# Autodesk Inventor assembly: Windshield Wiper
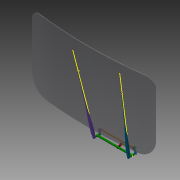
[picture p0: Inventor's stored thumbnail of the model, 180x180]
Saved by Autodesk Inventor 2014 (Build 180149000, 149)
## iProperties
Created: 2006-03
Part Number: Windshield Wiper
Document SubType Name: Assembly
Designer: debonom
Mass: 23655.8 g
Surface Area: 27679.2 cm^2
Volume: 10299.3 cm^3
Density: 2.29683 g/cm^3
Author: debonom
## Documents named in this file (9)
- C:\Users\iTools\Desktop\tutorial files\Dynamic Simulation 4\Windshield Wiper.iam
- C:\Users\iTools\Desktop\tutorial files\Dynamic Simulation 4\Components\Windshield.ipt
- C:\Users\iTools\Desktop\tutorial files\Dynamic Simulation 4\Components\Brush.iam
- C:\Users\iTools\Desktop\tutorial files\Dynamic Simulation 4\Components\Crank Sway.ipt
- C:\Users\iTools\Desktop\tutorial files\Dynamic Simulation 4\Components\Crank Motor.ipt
- C:\Users\iTools\Desktop\tutorial files\Dynamic Simulation 4\Components\Wiper base Left.iam
- C:\Users\iTools\Desktop\tutorial files\Dynamic Simulation 4\Components\Wiper base Right.iam
- C:\Users\iTools\Desktop\tutorial files\Dynamic Simulation 4\Components\Crank Motor.iam
- C:\Users\iTools\Desktop\tutorial files\Dynamic Simulation 4\Components\Frame Wiper.ipt
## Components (9 placed, 7 different names)
1. Frame Wiper:1 — Mate:1, Mate:2, Mate:3, Mate:11, Mate:9, Mate:14, Mate:15, Angle DRIVE, Mate:16, Mate:19
2. Crank Motor:2 [sub-assembly] — Mate:15, Angle DRIVE, Mate:16, Mate:17
3. Wiper base Left:1 [sub-assembly] — Mate:14, Mate:4, Mate:5, Angle:2, Insert:2, Insert:3, Mate:19
4. Brush:1 [sub-assembly] — Mate:4, Mate:5, Angle:2
5. Wiper base Right:1 [sub-assembly] — Mate:11, Mate:9, Mate:12, Mate:13, Angle:3, Mate:18
6. Brush:2 [sub-assembly] — Mate:12, Mate:13, Angle:3
7. Crank Motor:1 — Insert:3, Mate:17
8. Crank Sway:1 — Insert:2, Mate:18
9. Windshield:1 — Mate:1, Mate:2, Mate:3
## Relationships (20: Mate 15, Angle 3, Insert 2)
- Mate:1: Frame Wiper:1 ↔ Windshield:1
- Mate:2: Frame Wiper:1 ↔ Windshield:1
- Mate:3: Frame Wiper:1 ↔ Windshield:1
- Mate:14: Frame Wiper:1 ↔ Wiper base Left:1
- Mate:4: Wiper base Left:1 ↔ Brush:1
- Mate:5: Wiper base Left:1 ↔ Brush:1
- Angle:2: Wiper base Left:1 ↔ Brush:1
- Mate:11: Frame Wiper:1 ↔ Wiper base Right:1
- Mate:9: Frame Wiper:1 ↔ Wiper base Right:1
- Mate:12: Wiper base Right:1 ↔ Brush:2
- Mate:13: Wiper base Right:1 ↔ Brush:2
- Angle:3: Wiper base Right:1 ↔ Brush:2
- Insert:2: Wiper base Left:1 ↔ Crank Sway:1
- Insert:3: Wiper base Left:1 ↔ Crank Motor:1
- Mate:15: Frame Wiper:1 ↔ Crank Motor:2
- Angle DRIVE: Frame Wiper:1 ↔ Crank Motor:2
- Mate:16: Frame Wiper:1 ↔ Crank Motor:2
- Mate:17: Crank Motor:2 ↔ Crank Motor:1
- Mate:18: Wiper base Right:1 ↔ Crank Sway:1
- Mate:19: Frame Wiper:1 ↔ Wiper base Left:1
